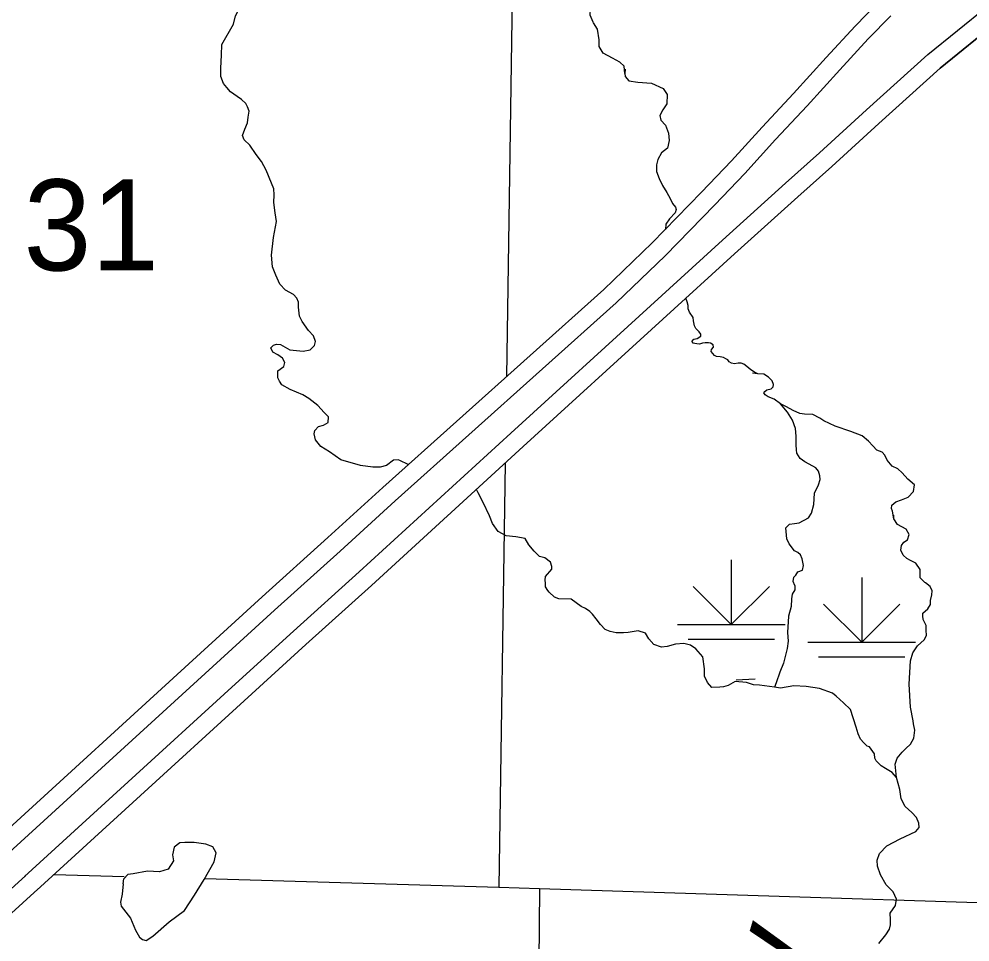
# Model space of a CAD drawing. Extents: x 8749 to 11879, y 13275 to 15339.
# Drawn here: x 10379.3 to 10467.6, y 13966.9 to 14052.6 of the extents above; entities that cross this region are included whole.
import ezdxf

# ---------------------------------------------------------------- set-up
doc = ezdxf.new("R2010")
doc.units = 0
for name, color, linetype in [('Level 19', 7, 'Continuous'), ('Level 35', 7, 'Continuous'), ('Level 4', 7, 'Continuous'), ('Level 44', 7, 'Continuous'), ('Level 5', 7, 'Continuous')]:
    doc.layers.add(name, color=color, linetype=linetype)

msp = doc.modelspace()

# ---------------------------------------------------------------- linework, layer by layer
at = {"layer": 'Level 19'}
for p, q in [((10413.093, 14009.096), (10433.6, 14027.476)), ((10413.093, 14009.096), (10433.6, 14027.476)), ((10414.24, 14007.842), (10434.745, 14026.219)), ((10434.745, 14026.219), (10414.24, 14007.842)), ((10424.994, 14014.147), (10437.941, 14025.959)), ((10424.994, 14014.147), (10437.941, 14025.959)), ((10426.139, 14012.891), (10439.087, 14024.703)), ((10439.087, 14024.703), (10426.139, 14012.891))]:
    msp.add_line(p, q, dxfattribs=at)
for points in [[(10463.693, 14049.259), (10469.186, 14053.722), (10475.411, 14058.912), (10480.219, 14062.792), (10484.918, 14066.585)], [(10463.693, 14049.259), (10469.186, 14053.722), (10475.411, 14058.912), (10480.219, 14062.792), (10484.918, 14066.585)], [(10464.829, 14047.994), (10470.267, 14052.409), (10476.489, 14057.597), (10481.287, 14061.469), (10485.986, 14065.263)], [(10485.986, 14065.263), (10481.287, 14061.469), (10476.489, 14057.597), (10470.267, 14052.409), (10464.829, 14047.994)], [(10445.472, 14039.396), (10448.303, 14042.519), (10451.232, 14045.663), (10454.257, 14048.981), (10456.932, 14051.901), (10459.061, 14054.055)], [(10445.472, 14039.396), (10448.303, 14042.519), (10451.232, 14045.663), (10454.257, 14048.981), (10456.932, 14051.901), (10459.061, 14054.055)], [(10446.699, 14038.22), (10449.554, 14041.369), (10452.482, 14044.511), (10455.512, 14047.835), (10458.164, 14050.729), (10460.27, 14052.86)], [(10460.27, 14052.86), (10458.164, 14050.729), (10455.512, 14047.835), (10452.482, 14044.511), (10449.554, 14041.369), (10446.699, 14038.22)], [(10450.485, 14037.325), (10453.627, 14040.148), (10457.991, 14044.141), (10463.693, 14049.259)], [(10450.485, 14037.325), (10453.627, 14040.148), (10457.991, 14044.141), (10463.693, 14049.259)], [(10451.624, 14036.063), (10454.769, 14038.889), (10459.132, 14042.881), (10464.829, 14047.994)], [(10464.829, 14047.994), (10459.132, 14042.881), (10454.769, 14038.889), (10451.624, 14036.063)], [(10433.6, 14027.476), (10438.112, 14031.782), (10442.695, 14036.499), (10445.472, 14039.396)], [(10433.6, 14027.476), (10438.112, 14031.782), (10442.695, 14036.499), (10445.472, 14039.396)], [(10434.745, 14026.219), (10439.309, 14030.575), (10443.919, 14035.319), (10446.699, 14038.22)], [(10446.699, 14038.22), (10443.919, 14035.319), (10439.309, 14030.575), (10434.745, 14026.219)], [(10437.941, 14025.959), (10444.617, 14032.026), (10450.485, 14037.325)], [(10437.941, 14025.959), (10444.617, 14032.026), (10450.485, 14037.325)], [(10439.087, 14024.703), (10445.758, 14030.766), (10451.624, 14036.063)], [(10451.624, 14036.063), (10445.758, 14030.766), (10439.087, 14024.703)], [(10399.081, 13990.557), (10404.799, 13995.771), (10410.893, 14001.256), (10424.994, 14014.147)], [(10426.139, 14012.891), (10412.035, 13999.997), (10405.94, 13994.511), (10400.227, 13989.301)], [(10396.183, 13993.733), (10401.912, 13998.958), (10408.004, 14004.44), (10413.093, 14009.096)], [(10414.24, 14007.842), (10409.146, 14003.181), (10403.053, 13997.698), (10397.329, 13992.477)], [(10376.934, 13976.16), (10396.183, 13993.733)], [(10397.329, 13992.477), (10378.08, 13974.904)], [(10379.833, 13972.984), (10399.081, 13990.557)], [(10400.227, 13989.301), (10380.979, 13971.729)], [(10292.381, 13893.383), (10379.95, 13973.091)], [(10381.087, 13971.827), (10293.525, 13892.125)]]:
    msp.add_lwpolyline(points, dxfattribs=at)
at = {"layer": 'Level 35'}
for points in [[(10398.157, 14050.203), (10399.229, 14052.095), (10399.428, 14052.844), (10399.753, 14053.494), (10399.878, 14053.944), (10400.177, 14054.194), (10400.452, 14054.469), (10400.901, 14054.519), (10401.5, 14054.544), (10402.449, 14054.893), (10402.899, 14055.268), (10403.173, 14055.693), (10403.198, 14056.843), (10403.023, 14057.417), (10402.948, 14057.892), (10402.549, 14058.392), (10402.025, 14058.992), (10401.6, 14059.516), (10401.451, 14059.941), (10401.301, 14061.191), (10401.226, 14061.915), (10401.525, 14062.69)], [(10435.558, 14047.52), (10435.508, 14048.185), (10435.108, 14048.559), (10434.409, 14048.934), (10433.561, 14049.384), (10433.186, 14050.009), (10433.186, 14050.634), (10433.011, 14051.633), (10432.662, 14052.208), (10432.612, 14052.283), (10432.337, 14052.933), (10432.362, 14053.482), (10433.186, 14054.282), (10434.659, 14055.107), (10436.232, 14055.931), (10436.956, 14056.606), (10437.405, 14057.281), (10438.054, 14058.805)], [(10402.968, 14035.536), (10402.998, 14036.244), (10402.973, 14036.794), (10402.774, 14037.318), (10402.274, 14038.543), (10401.85, 14039.343), (10401.351, 14039.992), (10400.751, 14040.842), (10400.227, 14041.342), (10400.077, 14041.766), (10400.277, 14042.341), (10400.527, 14042.916), (10400.602, 14043.441), (10400.677, 14044.016), (10400.527, 14044.415), (10400.377, 14044.715), (10399.978, 14045.09), (10399.578, 14045.365), (10398.954, 14045.79), (10398.604, 14046.215), (10398.305, 14046.564), (10398.055, 14047.214), (10398.055, 14048.014), (10398.13, 14049.213), (10398.157, 14050.203)], [(10435.608, 14047.92), (10435.558, 14047.52), (10435.583, 14047.22), (10435.932, 14046.82), (10436.756, 14046.695), (10438.054, 14046.595), (10439.128, 14046.12), (10439.502, 14045.571), (10439.477, 14044.696), (10439.078, 14044.146), (10438.803, 14043.596), (10438.903, 14043.172), (10439.328, 14042.697), (10439.627, 14041.972), (10439.677, 14041.297), (10439.527, 14040.573), (10438.953, 14040.148), (10438.629, 14039.523), (10438.504, 14039.023), (10438.504, 14038.998), (10438.504, 14038.424), (10438.753, 14037.749), (10439.053, 14037.099), (10439.452, 14036.474), (10439.777, 14035.9), (10440.002, 14035.45), (10440.276, 14035.1), (10440.326, 14034.875), (10440.226, 14034.575), (10439.702, 14034.025), (10439.378, 14033.526), (10439.334, 14033.04)], [(10404.791, 14027), (10404.067, 14027.39), (10403.543, 14027.965), (10403.168, 14028.789), (10402.869, 14029.564), (10402.769, 14030.664), (10402.944, 14032.288), (10403.218, 14033.787), (10403.118, 14034.587), (10402.968, 14035.536)], [(10403.343, 14019.903), (10403.917, 14020.328), (10403.992, 14020.703), (10403.792, 14021.103), (10403.343, 14021.402), (10402.894, 14021.652), (10402.694, 14022.052), (10402.944, 14022.302), (10403.218, 14022.402), (10403.593, 14022.352), (10404.466, 14021.877), (10405.715, 14021.727), (10406.339, 14021.877), (10406.763, 14022.252), (10406.838, 14022.627), (10406.663, 14023.177), (10406.189, 14023.651), (10405.615, 14024.501), (10405.365, 14025.001), (10405.265, 14025.826), (10405.265, 14026.275), (10405.116, 14026.65), (10404.791, 14027)], [(10442.267, 14022.902), (10442.629, 14023.119), (10442.604, 14023.306), (10442.455, 14023.531), (10442.155, 14023.843), (10442.043, 14024.093), (10441.943, 14024.543), (10441.893, 14024.868), (10441.556, 14025.368), (10441.456, 14025.68), (10441.456, 14025.98), (10441.356, 14026.305), (10441.225, 14026.646)], [(10447.918, 14019.641), (10447.61, 14019.779), (10447.261, 14020.016), (10446.899, 14020.304), (10446.611, 14020.541), (10446.349, 14020.616), (10446.1, 14020.641), (10445.75, 14020.566), (10445.476, 14020.616), (10445.238, 14020.766), (10445.138, 14020.928), (10444.951, 14021.041), (10444.714, 14021.153), (10444.427, 14021.203), (10444.077, 14021.241), (10443.878, 14021.353), (10443.591, 14021.703), (10443.603, 14021.903), (10443.803, 14022.115), (10443.765, 14022.315), (10443.528, 14022.478), (10443.341, 14022.528), (10443.016, 14022.528), (10442.767, 14022.478), (10442.48, 14022.403), (10442.242, 14022.415), (10442.068, 14022.44), (10441.918, 14022.49), (10441.818, 14022.64), (10441.843, 14022.765), (10441.98, 14022.852), (10442.267, 14022.902)], [(10404.491, 14018.189), (10403.717, 14018.629), (10403.493, 14018.954), (10403.343, 14019.253), (10403.343, 14019.478), (10403.343, 14019.903)], [(10450.003, 14016.861), (10449.441, 14017.28), (10448.88, 14017.517), (10448.593, 14017.692), (10448.468, 14017.867), (10448.555, 14017.992), (10448.755, 14018.142), (10449.154, 14018.254), (10449.342, 14018.429), (10449.366, 14018.642), (10449.242, 14018.992), (10448.892, 14019.316), (10448.48, 14019.604), (10447.918, 14019.641), (10447.419, 14019.704)], [(10414.673, 14011.601), (10414.528, 14011.667), (10414.078, 14011.617), (10413.454, 14011.117), (10412.855, 14010.992), (10412.181, 14010.967), (10411.032, 14011.142), (10409.185, 14011.667), (10408.136, 14012.391), (10407.338, 14012.891), (10406.838, 14013.516), (10406.738, 14014.066), (10406.788, 14014.39), (10407.113, 14014.765), (10407.587, 14014.865), (10408.012, 14015.115), (10408.062, 14015.64), (10407.662, 14016.04), (10407.063, 14016.689), (10406.214, 14017.339), (10405.665, 14017.689), (10404.491, 14018.189)], [(10453.285, 14010.926), (10452.687, 14011.251), (10452.263, 14011.463), (10451.838, 14011.788), (10451.539, 14012.263), (10451.489, 14012.601), (10451.464, 14013.038), (10451.476, 14013.862), (10451.414, 14014.562), (10451.114, 14015.349), (10450.652, 14016.087), (10450.003, 14016.861)], [(10451.183, 14016.224), (10450.565, 14016.568), (10450.003, 14016.861)], [(10460.545, 14006.188), (10460.42, 14006.903), (10460.32, 14007.153), (10460.345, 14007.453), (10460.72, 14007.753), (10461.244, 14007.953), (10461.868, 14008.203), (10462.368, 14008.727), (10462.443, 14009.352), (10461.843, 14009.877), (10461.294, 14010.452), (10460.92, 14010.826), (10460.37, 14011.076), (10459.921, 14011.626), (10459.696, 14012.101), (10459.447, 14012.376), (10458.947, 14012.551), (10458.573, 14012.95), (10458.173, 14013.375), (10457.599, 14013.875), (10456.551, 14014.3), (10455.078, 14014.775), (10454.029, 14015.274), (10453.679, 14015.524), (10453.03, 14015.874), (10452.256, 14015.899), (10451.807, 14015.949), (10451.183, 14016.224)], [(10415.461, 14011.218), (10414.673, 14011.601)], [(10451.338, 14000.006), (10451.188, 14000.381), (10451.238, 14000.756), (10451.437, 14000.956), (10451.637, 14001.256), (10452.062, 14001.431), (10452.161, 14001.855), (10452.037, 14002.48), (10451.862, 14002.83), (10451.612, 14003.055), (10451.313, 14003.205), (10450.813, 14003.879), (10450.614, 14004.329), (10450.539, 14005.004), (10450.514, 14005.354), (10450.863, 14005.679), (10451.313, 14005.754), (10451.762, 14005.804), (10452.611, 14006.278), (10452.886, 14006.703), (10453.11, 14007.503), (10453.185, 14008.577), (10453.535, 14009.327), (10453.684, 14009.827), (10453.659, 14010.177), (10453.535, 14010.602), (10453.285, 14010.926)], [(10423.805, 14005.022), (10423.286, 14005.754), (10423.011, 14006.454), (10422.412, 14007.703), (10421.963, 14008.603), (10421.796, 14008.92)], [(10463.541, 13996.287), (10463.266, 13996.842), (10463.216, 13997.192), (10463.241, 13997.417), (10463.691, 13997.842), (10463.94, 13998.242), (10463.94, 13998.592), (10464.065, 13999.116), (10464.09, 13999.491), (10463.916, 13999.891), (10463.466, 14000.241), (10463.416, 14000.291), (10462.967, 14000.716), (10462.967, 14001.091), (10462.992, 14001.49), (10462.567, 14002.065), (10462.467, 14002.14), (10462.068, 14002.315), (10461.743, 14002.515), (10461.394, 14002.815), (10461.194, 14003.29), (10461.244, 14003.714), (10461.469, 14004.014), (10461.793, 14004.239), (10461.968, 14004.739), (10461.669, 14005.214), (10461.269, 14005.439), (10460.87, 14005.664), (10460.545, 14006.188), (10460.52, 14006.538)], [(10437.482, 13995.576), (10436.787, 13995.776), (10435.864, 13995.626), (10435.439, 13995.601), (10434.765, 13995.601), (10434.216, 13995.726), (10433.742, 13995.926), (10433.317, 13996.375), (10432.893, 13996.9), (10432.568, 13997.325), (10432.319, 13997.6), (10431.919, 13997.85), (10431.495, 13998.05), (10430.571, 13998.724), (10429.447, 13998.749), (10429.048, 13998.924), (10428.549, 13999.374), (10428.424, 13999.524), (10428.199, 13999.874), (10428.199, 14000.199), (10428.174, 14000.499), (10428.199, 14000.823), (10428.773, 14001.498), (10428.773, 14001.773), (10428.673, 14002.173), (10428.149, 14002.573), (10427.65, 14002.698), (10427.151, 14003.172), (10426.651, 14003.772), (10426.327, 14004.347), (10425.453, 14004.522), (10424.554, 14004.597), (10423.805, 14005.022)], [(10451.338, 14000.006), (10451.338, 13999.599), (10451.088, 13999.199), (10451.038, 13998.749), (10451.013, 13998.05), (10450.763, 13997.15), (10450.664, 13995.626), (10450.713, 13994.826), (10450.639, 13994.151)], [(10460.795, 13982.178), (10460.645, 13983.418), (10460.845, 13983.968), (10461.319, 13984.542), (10461.644, 13984.867), (10462.068, 13985.267), (10462.393, 13985.842), (10462.492, 13986.567), (10462.368, 13987.166), (10462.318, 13987.441), (10462.068, 13988.716), (10461.968, 13990.84), (10462.068, 13993.014), (10462.293, 13993.764), (10462.717, 13994.388), (10463.341, 13994.963), (10463.566, 13995.363), (10463.541, 13995.863), (10463.541, 13996.287)], [(10447.518, 13990.778), (10446.844, 13991.003), (10445.795, 13991.103), (10445.171, 13990.728), (10444.722, 13990.603), (10444.372, 13990.553), (10443.648, 13990.528), (10443.224, 13991.003), (10442.949, 13991.577), (10442.949, 13992.252), (10442.799, 13993.377), (10442.15, 13994.126), (10441.651, 13994.451), (10441.052, 13994.601), (10440.278, 13994.551), (10439.479, 13994.351), (10438.979, 13994.276), (10438.255, 13994.526), (10437.806, 13995.051), (10437.482, 13995.576)], [(10450.639, 13994.151), (10450.289, 13992.802), (10449.94, 13991.952), (10449.615, 13990.978), (10449.465, 13990.553)], [(10445.911, 13991.25), (10447.665, 13991.33)], [(10449.465, 13990.553), (10448.067, 13990.753), (10447.518, 13990.778)], [(10451.238, 13990.678), (10450.014, 13990.478), (10449.465, 13990.553)], [(10458.748, 13984.377), (10458.273, 13985.017), (10458.048, 13985.092), (10457.749, 13985.392), (10457.449, 13985.742), (10457.225, 13986.242), (10457.05, 13986.841), (10456.526, 13988.491), (10455.851, 13989.116), (10455.177, 13989.74), (10454.828, 13990.015), (10453.63, 13990.44), (10452.411, 13990.628), (10451.238, 13990.678)], [(10462.592, 13977.165), (10462.892, 13977.53), (10462.867, 13977.93), (10462.642, 13978.48), (10462.193, 13978.93), (10461.594, 13979.505), (10461.219, 13980.204), (10461.094, 13981.054), (10460.795, 13982.178), (10460.395, 13982.653), (10459.771, 13983.028), (10459.372, 13983.278), (10458.897, 13983.728), (10458.773, 13983.978), (10458.748, 13984.377)], [(10459.152, 13966.785), (10459.796, 13967.595), (10460.146, 13968.119), (10460.221, 13968.519), (10460.221, 13969.019), (10460.196, 13969.594), (10460.695, 13970.318), (10460.795, 13970.893), (10460.47, 13971.568), (10459.821, 13972.218), (10459.297, 13973.142), (10459.022, 13973.942), (10458.997, 13974.517), (10459.197, 13975.141), (10459.896, 13975.841), (10461.119, 13976.491), (10462.592, 13977.165)], [(10389.006, 13972.329), (10388.892, 13971.353), (10388.743, 13970.603), (10388.818, 13970.228), (10389.666, 13969.129), (10390.141, 13968.029), (10390.515, 13967.379), (10390.79, 13967.154), (10391.14, 13967.054), (10391.739, 13967.454), (10393.262, 13968.779), (10394.685, 13969.828), (10395.609, 13971.253), (10396.507, 13972.702), (10397.431, 13974.351), (10397.631, 13975.201), (10397.306, 13975.751), (10396.682, 13976.001), (10395.584, 13976.151), (10394.71, 13976.151), (10394.26, 13976.126), (10393.736, 13975.726), (10393.586, 13975.001), (10393.661, 13974.451), (10393.162, 13973.677), (10392.363, 13973.427), (10391.264, 13973.502), (10389.916, 13973.252), (10389.442, 13973.177)], [(10389.006, 13972.329), (10389.042, 13972.777), (10389.442, 13973.177)]]:
    msp.add_lwpolyline(points, dxfattribs=at)
at = {"layer": 'Level 4'}
for points in [[(10382.584, 13973.194), (10389.085, 13973.008)], [(10396.56, 13972.795), (10423.874, 13972.016), (10427.65, 13971.895), (10491.482, 13969.848), (10529.209, 13968.851), (10532.836, 13968.848), (10636.468, 13968.788), (10639.603, 13968.786), (10680.464, 13967.884)]]:
    msp.add_lwpolyline(points, dxfattribs=at)
at = {"layer": 'Level 44'}
for p, q in [((10445.446, 14002.375), (10445.446, 13996.375)), ((10457.554, 14000.726), (10457.554, 13994.726)), ((10445.446, 13996.375), (10441.91, 13999.911)), ((10445.446, 13996.375), (10448.981, 13999.911)), ((10457.554, 13994.726), (10454.019, 13998.262)), ((10457.554, 13994.726), (10461.09, 13998.262)), ((10440.446, 13996.375), (10450.446, 13996.375)), ((10441.446, 13995.012), (10449.446, 13995.012)), ((10452.554, 13994.726), (10462.554, 13994.726)), ((10453.554, 13993.363), (10461.554, 13993.363))]:
    msp.add_line(p, q, dxfattribs=at)
at = {"layer": 'Level 5'}
for points in [[(10425.477, 14079.513), (10424.58, 14019.392)], [(10424.461, 14011.357), (10423.874, 13972.016)], [(10427.65, 13971.895), (10427.224, 13924.19)]]:
    msp.add_lwpolyline(points, dxfattribs=at)

# ---------------------------------------------------------------- texts
at = {"layer": 'Level 35'}
msp.add_text('Sandy', height=8.448, rotation=73.55451, dxfattribs=at).set_placement((10444.611, 13936.411))
at = {"layer": 'Level 5'}
msp.add_text('31', height=8.448, dxfattribs=at).set_placement((10379.751, 14029.229))

doc.saveas('drawing.dxf')
